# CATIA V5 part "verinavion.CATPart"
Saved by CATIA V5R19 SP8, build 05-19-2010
Part number: verinavion
Bounding box of the stored display mesh (mm): x -40 to 80, y 160 to 240, z -30 to 30
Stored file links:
  C:\Users\rcousturie\Desktop\EU_thinkMotion\iao\IAO_MMS_Groupe1\flamrini\Lamrini_projet_IAO2011\Lamrini_projet_IAO2011\projet_iao_traindatterrissage\projet_iao_traindatterrissage\verinavion.CATPart
  C:\Users\rcousturie\Desktop\EU_thinkMotion\iao\IAO_MMS_Groupe1\flamrini\Lamrini_projet_IAO2011\Lamrini_projet_IAO2011\projet_iao_traindatterrissage\projet_iao_traindatterrissage\trainavion.CATProduct
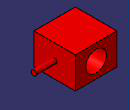
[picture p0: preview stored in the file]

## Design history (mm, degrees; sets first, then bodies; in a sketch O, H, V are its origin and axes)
Set1
  Sketch1 on yz-plane, origin (0, 0, 0), H (0, 1, 0), V (0, 0, 1)
    line L1 (160, 30) -> (240, 30)
    line L2 (240, 30) -> (240, -30)
    line L3 (240, -30) -> (160, -30)
    line L4 (160, -30) -> (160, 30)
    length L2 = 60
    horizontal: L1 H, L3 H
    vertical: L2 V, L4 V
Set2
  Line1 "axeverin": linked copy from another document
  Point1 "PointF": linked copy from another document
Body1 (main body)
  Pad1: profile Sketch1, direction (1, 0, 0), length 40, mirrored extent
  Sketch2 on face of Pad1 from Sketch1.L4, origin (0, 160, 0), H (1, 0, 0), V (0, 0, 1)
    point P1 (0, 0)
    intersected point E1 (0, 0) from Line1
    coincidence: E1 P1
  Hole1: placed by Sketch2, at (0, 160, 0) direction (0, 1, 0), diameter 40, through (limit type 3)
  Sketch3 on end face of Pad1, origin (40, 0, 0), H (0, 1, 0), V (0, 0, 1)
    circle A1 centre (200, 0) radius 5
    point P1 (200, 0)
    reference projected point E1 (200, 0) from Point1
    radius A1 = 5
    coincidence: P1 E1
  Pad2: profile Sketch3, direction (1, 0, 0), length 40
